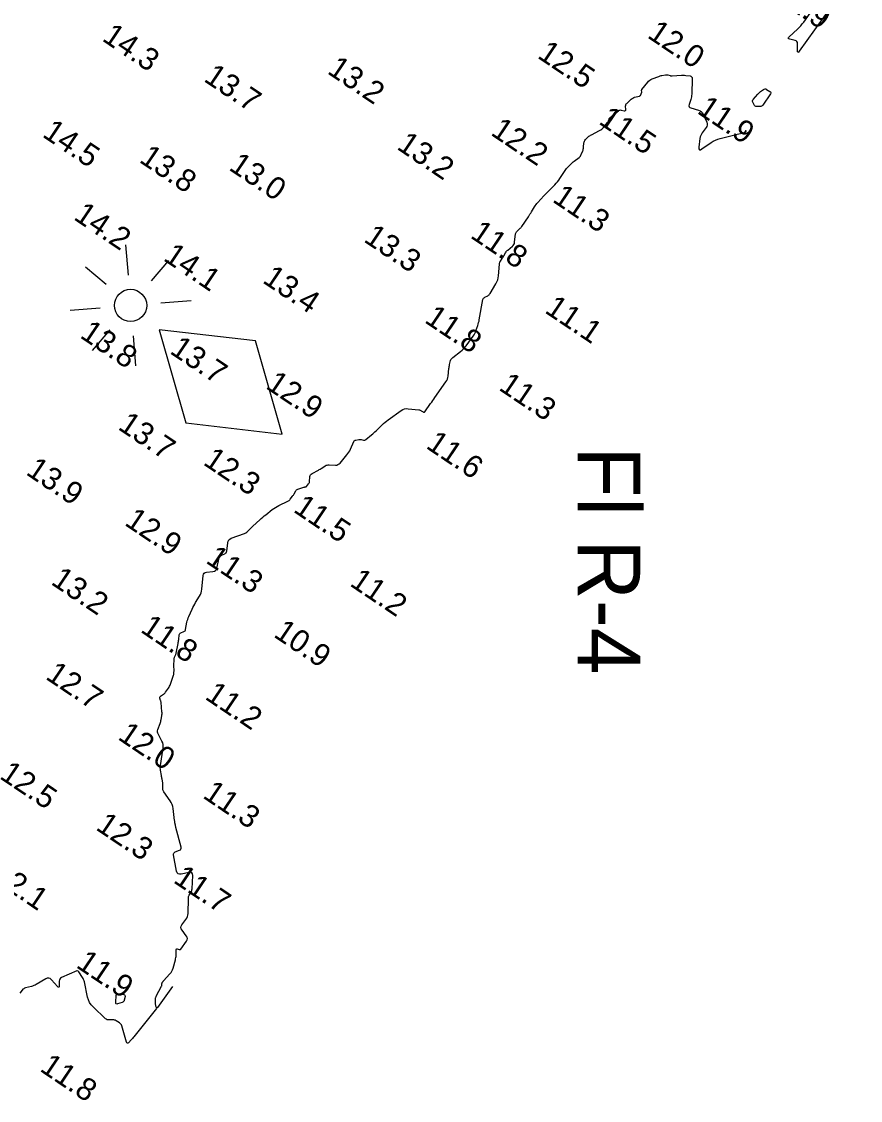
# Model space of a CAD drawing. Extents: x 815352 to 820877, y 582403 to 597439.
# Drawn here: x 816866.2 to 817053.6, y 584137 to 584378.1 of the extents above; entities that cross this region are included whole.
import ezdxf

# ---------------------------------------------------------------- set-up
doc = ezdxf.new("R2010")
doc.units = 0
for name, color, linetype in [('V-CHAN-NAID', 7, 'Continuous'), ('V-CONT-EL12', 7, 'Continuous'), ('V-TOPO-SOUN', 7, 'Continuous')]:
    doc.layers.add(name, color=color, linetype=linetype)

msp = doc.modelspace()

# ---------------------------------------------------------------- linework, layer by layer
at = {"layer": 'V-CHAN-NAID'}
for p, q in [((816889.49, 584328.21), (816890.04, 584321.45)), ((816895.25, 584320.17), (816899.14, 584324.74)), ((816885.1, 584319.34), (816880.53, 584323.23)), ((816897.36, 584315.23), (816904.12, 584315.78)), ((816877.06, 584313.58), (816883.82, 584314.13)), ((816885.93, 584309.19), (816882.04, 584304.62)), ((816891.14, 584307.91), (816891.69, 584301.15))]:
    msp.add_line(p, q, dxfattribs=at)
msp.add_lwpolyline([(816896.99, 584309.24), (816902.94, 584288.44), (816924.43, 584285.93), (816918.48, 584306.73)], close=True, dxfattribs=at)
msp.add_circle((816890.59, 584314.68), 3.6, dxfattribs=at)
at = {"layer": 'V-CONT-EL12'}
for points in [[(817053.62, 584390.67), (817039.95, 584371.49), (817039.77, 584371.27), (817039.64, 584371.23), (817039.57, 584371.34), (817039.55, 584371.62), (817039.59, 584373.18), (817039.55, 584373.45), (817039.45, 584373.66), (817039.27, 584373.82), (817039.01, 584373.91), (817037.83, 584374.18), (817037.6, 584374.26), (817037.5, 584374.38), (817037.53, 584374.53), (817037.69, 584374.72), (817039.57, 584376.45), (817039.95, 584376.81), (817040.31, 584377.2), (817040.64, 584377.6), (817040.96, 584378.02), (817042.91, 584380.77)], [(816899.93, 584162.43), (816896.59, 584157.79), (816896.5, 584157.69), (816896.42, 584157.66), (816896.36, 584157.72), (816896.32, 584157.85), (816896.16, 584158.57), (816896.14, 584158.72), (816896.12, 584158.86), (816896.12, 584159.01), (816896.12, 584159.15), (816896.17, 584159.74), (816896.19, 584159.89), (816896.22, 584160.03), (816896.27, 584160.17), (816896.33, 584160.3), (816897.52, 584162.5), (816897.55, 584162.57), (816897.57, 584162.63), (816897.59, 584162.7), (816897.59, 584162.77), (816897.59, 584163.08), (816897.59, 584163.14), (816897.61, 584163.2), (816897.63, 584163.25), (816897.66, 584163.31), (816897.8, 584163.51), (816897.84, 584163.56), (816897.87, 584163.61), (816897.91, 584163.66), (816897.95, 584163.71), (816899.39, 584165.26), (816899.63, 584165.55), (816899.82, 584165.85), (816899.98, 584166.18), (816900.1, 584166.53), (816900.6, 584168.41), (816900.66, 584168.65), (816900.71, 584168.9), (816900.74, 584169.15), (816900.75, 584169.4), (816900.79, 584170.7), (816900.81, 584170.8), (816900.85, 584170.85), (816900.92, 584170.87), (816901.02, 584170.86), (816901.45, 584170.71), (816901.56, 584170.69), (816901.65, 584170.7), (816901.73, 584170.74), (816901.8, 584170.82), (816903.06, 584172.56), (816903.23, 584172.87), (816903.28, 584173.19), (816903.22, 584173.5), (816903.04, 584173.81), (816902.08, 584175.06), (816901.91, 584175.36), (816901.85, 584175.66), (816901.9, 584175.95), (816902.07, 584176.25), (816902.96, 584177.45), (816903.16, 584177.76), (816903.3, 584178.09), (816903.39, 584178.43), (816903.43, 584178.8), (816903.5, 584182.15), (816903.52, 584182.34), (816903.56, 584182.53), (816903.62, 584182.71), (816903.71, 584182.88), (816904.1, 584183.55), (816904.19, 584183.72), (816904.26, 584183.9), (816904.3, 584184.09), (816904.32, 584184.28), (816904.48, 584187.26), (816904.45, 584187.64), (816904.3, 584187.88), (816904.04, 584187.98), (816903.66, 584187.96), (816901.92, 584187.56), (816901.53, 584187.53), (816901.23, 584187.64), (816901.01, 584187.87), (816900.88, 584188.25), (816900.2, 584191.85), (816900.18, 584192.08), (816900.24, 584192.27), (816900.37, 584192.42), (816900.57, 584192.53), (816901.52, 584192.9), (816901.72, 584193.01), (816901.85, 584193.16), (816901.9, 584193.35), (816901.87, 584193.57), (816900.73, 584198.01), (816900.69, 584198.13), (816900.66, 584198.26), (816900.64, 584198.39), (816900.61, 584198.51), (816900.51, 584199.02), (816900.49, 584199.15), (816900.46, 584199.28), (816900.44, 584199.41), (816900.43, 584199.54), (816900.09, 584202.24), (816900, 584202.7), (816899.86, 584203.14), (816899.67, 584203.56), (816899.43, 584203.95), (816898, 584205.98), (816897.91, 584206.13), (816897.85, 584206.28), (816897.82, 584206.44), (816897.81, 584206.61), (816897.82, 584207.3), (816897.81, 584207.47), (816897.8, 584207.64), (816897.79, 584207.81), (816897.76, 584207.98), (816897.61, 584208.81), (816897.58, 584209.01), (816897.54, 584209.2), (816897.51, 584209.4), (816897.47, 584209.59), (816897.27, 584210.79), (816897.24, 584211.06), (816897.22, 584211.32), (816897.23, 584211.59), (816897.26, 584211.85), (816897.85, 584215.8), (816897.88, 584216.18), (816897.85, 584216.55), (816897.76, 584216.91), (816897.6, 584217.26), (816896.8, 584218.77), (816896.68, 584219.05), (816896.63, 584219.33), (816896.64, 584219.62), (816896.71, 584219.91), (816897.19, 584221.26), (816897.26, 584221.47), (816897.32, 584221.68), (816897.37, 584221.9), (816897.41, 584222.11), (816897.56, 584222.98), (816897.6, 584223.2), (816897.61, 584223.42), (816897.61, 584223.64), (816897.6, 584223.86), (816897.42, 584225.89), (816897.4, 584226.02), (816897.38, 584226.15), (816897.35, 584226.28), (816897.31, 584226.41), (816897.15, 584226.92), (816897.13, 584227.05), (816897.14, 584227.15), (816897.2, 584227.25), (816897.29, 584227.33), (816897.92, 584227.76), (816898.06, 584227.86), (816898.19, 584227.97), (816898.3, 584228.1), (816898.41, 584228.23), (816899.06, 584229.15), (816899.19, 584229.36), (816899.31, 584229.57), (816899.41, 584229.79), (816899.5, 584230.02), (816900.18, 584232.06), (816900.22, 584232.18), (816900.24, 584232.29), (816900.26, 584232.41), (816900.27, 584232.53), (816900.31, 584233.06), (816900.31, 584233.15), (816900.31, 584233.24), (816900.3, 584233.33), (816900.29, 584233.42), (816900.25, 584233.78), (816900.24, 584233.87), (816900.24, 584233.96), (816900.24, 584234.05), (816900.24, 584234.14), (816900.31, 584235.63), (816900.32, 584235.75), (816900.34, 584235.86), (816900.38, 584235.98), (816900.42, 584236.09), (816900.63, 584236.53), (816900.68, 584236.64), (816900.73, 584236.75), (816900.76, 584236.87), (816900.79, 584236.98), (816901.2, 584239.09), (816901.24, 584239.32), (816901.28, 584239.55), (816901.31, 584239.78), (816901.34, 584240.01), (816901.45, 584241.06), (816901.49, 584241.23), (816901.56, 584241.36), (816901.67, 584241.46), (816901.82, 584241.53), (816902.49, 584241.77), (816902.64, 584241.85), (816902.75, 584241.95), (816902.84, 584242.08), (816902.88, 584242.24), (816903.19, 584243.86), (816903.26, 584244.19), (816903.35, 584244.51), (816903.46, 584244.82), (816903.59, 584245.13), (816904.35, 584246.81), (816904.52, 584247.19), (816904.71, 584247.56), (816904.91, 584247.92), (816905.12, 584248.28), (816905.99, 584249.71), (816906.19, 584250.07), (816906.34, 584250.45), (816906.45, 584250.84), (816906.51, 584251.25), (816906.79, 584254.31), (816906.87, 584254.62), (816907.02, 584254.86), (816907.26, 584255.01), (816907.57, 584255.08), (816909, 584255.19), (816909.32, 584255.26), (816909.57, 584255.41), (816909.76, 584255.64), (816909.87, 584255.95), (816910.4, 584258.27), (816910.47, 584258.46), (816910.57, 584258.62), (816910.7, 584258.74), (816910.88, 584258.84), (816911.64, 584259.18), (816911.81, 584259.28), (816911.94, 584259.41), (816912.03, 584259.57), (816912.07, 584259.76), (816912.28, 584261.61), (816912.37, 584261.96), (816912.53, 584262.25), (816912.77, 584262.47), (816913.09, 584262.63), (816916, 584263.67), (816916.19, 584263.75), (816916.37, 584263.85), (816916.54, 584263.98), (816916.69, 584264.12), (816917.27, 584264.74), (816917.42, 584264.9), (816917.57, 584265.05), (816917.72, 584265.2), (816917.88, 584265.34), (816919.47, 584266.78), (816919.79, 584267.06), (816920.12, 584267.34), (816920.45, 584267.62), (816920.78, 584267.88), (816922.22, 584269.04), (816922.57, 584269.3), (816922.93, 584269.54), (816923.3, 584269.75), (816923.68, 584269.95), (816925.68, 584270.89), (816925.85, 584270.99), (816926, 584271.1), (816926.14, 584271.22), (816926.27, 584271.37), (816926.76, 584272.02), (816926.87, 584272.16), (816926.97, 584272.3), (816927.06, 584272.45), (816927.14, 584272.6), (816927.47, 584273.21), (816927.57, 584273.35), (816927.68, 584273.47), (816927.82, 584273.56), (816927.97, 584273.63), (816929.26, 584274.05), (816929.31, 584274.07), (816929.36, 584274.08), (816929.42, 584274.09), (816929.47, 584274.1), (816929.7, 584274.12), (816929.75, 584274.13), (816929.8, 584274.15), (816929.84, 584274.18), (816929.88, 584274.22), (816930.36, 584274.77), (816930.44, 584274.88), (816930.5, 584275), (816930.54, 584275.13), (816930.57, 584275.26), (816930.66, 584276.41), (816930.7, 584276.64), (816930.79, 584276.83), (816930.93, 584276.99), (816931.12, 584277.11), (816932.53, 584277.86), (816932.74, 584277.97), (816932.93, 584278.09), (816933.13, 584278.21), (816933.32, 584278.33), (816934.09, 584278.83), (816934.29, 584278.94), (816934.5, 584279.01), (816934.71, 584279.05), (816934.94, 584279.06), (816936.35, 584278.99), (816936.65, 584279.01), (816936.92, 584279.09), (816937.16, 584279.24), (816937.38, 584279.44), (816938.93, 584281.3), (816939.15, 584281.58), (816939.36, 584281.89), (816939.54, 584282.2), (816939.7, 584282.53), (816940.49, 584284.26), (816940.56, 584284.39), (816940.66, 584284.49), (816940.78, 584284.55), (816940.92, 584284.59), (816941.55, 584284.7), (816941.69, 584284.71), (816941.83, 584284.72), (816941.97, 584284.71), (816942.1, 584284.69), (816942.65, 584284.58), (816942.79, 584284.57), (816942.92, 584284.58), (816943.03, 584284.63), (816943.15, 584284.7), (816944.44, 584285.77), (816944.7, 584285.98), (816944.94, 584286.2), (816945.18, 584286.42), (816945.42, 584286.65), (816946.79, 584287.98), (816947.11, 584288.28), (816947.43, 584288.56), (816947.76, 584288.82), (816948.11, 584289.08), (816951.02, 584291.18), (816951.39, 584291.4), (816951.78, 584291.54), (816952.19, 584291.61), (816952.62, 584291.6), (816955.01, 584291.33), (816955.14, 584291.31), (816955.27, 584291.27), (816955.39, 584291.22), (816955.5, 584291.15), (816955.95, 584290.86), (816956.05, 584290.81), (816956.15, 584290.8), (816956.24, 584290.84), (816956.33, 584290.93), (816957.62, 584292.73), (816957.86, 584293.06), (816958.1, 584293.4), (816958.34, 584293.74), (816958.57, 584294.08), (816961.04, 584297.6), (816961.22, 584297.9), (816961.37, 584298.22), (816961.47, 584298.56), (816961.52, 584298.9), (816961.69, 584300.6), (816961.72, 584300.83), (816961.76, 584301.05), (816961.8, 584301.27), (816961.85, 584301.48), (816962.08, 584302.35), (816962.16, 584302.56), (816962.26, 584302.75), (816962.39, 584302.92), (816962.56, 584303.06), (816964.32, 584304.41), (816964.66, 584304.69), (816964.98, 584305), (816965.28, 584305.32), (816965.55, 584305.67), (816967.13, 584307.84), (816967.31, 584308.11), (816967.47, 584308.39), (816967.61, 584308.68), (816967.72, 584308.98), (816968.15, 584310.21), (816968.26, 584310.51), (816968.34, 584310.83), (816968.42, 584311.14), (816968.48, 584311.46), (816969.29, 584315.97), (816969.34, 584316.14), (816969.43, 584316.29), (816969.54, 584316.41), (816969.69, 584316.51), (816970.36, 584316.84), (816970.52, 584316.94), (816970.66, 584317.05), (816970.79, 584317.18), (816970.89, 584317.33), (816972.2, 584319.51), (816972.42, 584319.93), (816972.59, 584320.37), (816972.71, 584320.83), (816972.77, 584321.31), (816972.97, 584323.93), (816973, 584324.1), (816973.04, 584324.26), (816973.11, 584324.42), (816973.2, 584324.57), (816973.6, 584325.14), (816973.7, 584325.28), (816973.79, 584325.43), (816973.88, 584325.58), (816973.97, 584325.73), (816974.37, 584326.46), (816974.47, 584326.62), (816974.58, 584326.78), (816974.71, 584326.92), (816974.86, 584327.05), (816975.87, 584327.89), (816976.07, 584328.08), (816976.22, 584328.3), (816976.32, 584328.55), (816976.38, 584328.82), (816976.6, 584330.66), (816976.63, 584330.84), (816976.7, 584331), (816976.79, 584331.15), (816976.92, 584331.28), (816977.47, 584331.78), (816977.61, 584331.91), (816977.74, 584332.04), (816977.85, 584332.18), (816977.96, 584332.33), (816979.46, 584334.51), (816979.64, 584334.78), (816979.81, 584335.05), (816979.98, 584335.32), (816980.15, 584335.59), (816980.8, 584336.69), (816980.97, 584336.96), (816981.16, 584337.22), (816981.35, 584337.47), (816981.56, 584337.71), (816982.88, 584339.15), (816983.17, 584339.47), (816983.47, 584339.78), (816983.77, 584340.09), (816984.07, 584340.4), (816985.36, 584341.66), (816985.66, 584341.98), (816985.95, 584342.32), (816986.23, 584342.67), (816986.48, 584343.03), (816987.84, 584345.08), (816987.96, 584345.26), (816988.09, 584345.43), (816988.24, 584345.59), (816988.39, 584345.74), (816989.01, 584346.35), (816989.17, 584346.5), (816989.33, 584346.64), (816989.49, 584346.78), (816989.66, 584346.92), (816990.77, 584347.77), (816990.93, 584347.91), (816991.07, 584348.06), (816991.18, 584348.24), (816991.27, 584348.42), (816991.59, 584349.21), (816991.66, 584349.41), (816991.72, 584349.61), (816991.76, 584349.82), (816991.79, 584350.03), (816991.87, 584350.99), (816991.91, 584351.2), (816991.98, 584351.39), (816992.08, 584351.57), (816992.22, 584351.73), (816992.83, 584352.34), (816992.99, 584352.48), (816993.16, 584352.61), (816993.34, 584352.73), (816993.53, 584352.83), (816995.37, 584353.75), (816995.61, 584353.89), (816995.83, 584354.05), (816996.04, 584354.23), (816996.22, 584354.43), (816997.13, 584355.55), (816997.2, 584355.64), (816997.25, 584355.73), (816997.3, 584355.82), (816997.33, 584355.92), (816997.46, 584356.32), (816997.5, 584356.42), (816997.55, 584356.51), (816997.62, 584356.59), (816997.69, 584356.66), (816999.58, 584358.2), (816999.72, 584358.3), (816999.87, 584358.35), (817000.03, 584358.37), (817000.19, 584358.35), (817000.87, 584358.19), (817001.02, 584358.18), (817001.13, 584358.22), (817001.19, 584358.32), (817001.2, 584358.46), (817001.18, 584359.22), (817001.19, 584359.4), (817001.24, 584359.56), (817001.32, 584359.71), (817001.44, 584359.84), (817002.43, 584360.77), (817002.6, 584360.91), (817002.78, 584361.02), (817002.97, 584361.12), (817003.18, 584361.19), (817004.26, 584361.48), (817004.35, 584361.51), (817004.43, 584361.56), (817004.49, 584361.63), (817004.54, 584361.72), (817004.74, 584362.16), (817004.76, 584362.23), (817004.77, 584362.29), (817004.78, 584362.35), (817004.77, 584362.42), (817004.74, 584362.68), (817004.74, 584362.74), (817004.75, 584362.8), (817004.77, 584362.86), (817004.81, 584362.91), (817006.1, 584364.58), (817006.31, 584364.82), (817006.55, 584365.02), (817006.81, 584365.19), (817007.1, 584365.32), (817008.57, 584365.88), (817008.74, 584365.94), (817008.91, 584365.99), (817009.09, 584366.04), (817009.27, 584366.07), (817010.09, 584366.21), (817010.22, 584366.22), (817010.35, 584366.22), (817010.47, 584366.21), (817010.59, 584366.18), (817011.09, 584366.04), (817011.21, 584366.01), (817011.34, 584366), (817011.46, 584365.99), (817011.59, 584365.99), (817013.62, 584366.14), (817013.87, 584366.15), (817014.11, 584366.15), (817014.35, 584366.13), (817014.59, 584366.1), (817015.56, 584365.98), (817015.77, 584365.92), (817015.92, 584365.8), (817016, 584365.64), (817016.03, 584365.42), (817015.93, 584361.93), (817015.91, 584361.63), (817015.87, 584361.33), (817015.81, 584361.03), (817015.72, 584360.74), (817015.35, 584359.57), (817015.3, 584359.31), (817015.35, 584359.09), (817015.5, 584358.93), (817015.75, 584358.82), (817017.45, 584358.32), (817017.8, 584358.18), (817018.1, 584357.97), (817018.34, 584357.71), (817018.53, 584357.37), (817019.31, 584355.62), (817019.41, 584355.3), (817019.42, 584354.99), (817019.34, 584354.69), (817019.16, 584354.41), (817018.29, 584353.28), (817018.09, 584352.99), (817017.94, 584352.68), (817017.83, 584352.36), (817017.77, 584352.01), (817017.55, 584350.03), (817017.55, 584349.68), (817017.66, 584349.49), (817017.87, 584349.48), (817018.19, 584349.65), (817020.26, 584351.07), (817020.74, 584351.36), (817021.23, 584351.61), (817021.74, 584351.82), (817022.28, 584351.98), (817024.98, 584352.66), (817025.26, 584352.73), (817025.54, 584352.8), (817025.82, 584352.87), (817026.1, 584352.93), (817027.23, 584353.18), (817027.49, 584353.27), (817027.73, 584353.4), (817027.93, 584353.57), (817028.11, 584353.79), (817027.79, 584353.31)], [(816896.39, 584157.51), (816891.29, 584151.19), (816891.15, 584151.02), (816891.01, 584150.86), (816890.86, 584150.69), (816890.72, 584150.53), (816890.13, 584149.89), (816889.99, 584149.78), (816889.87, 584149.75), (816889.78, 584149.83), (816889.7, 584149.99), (816888.6, 584153.66), (816888.53, 584153.85), (816888.42, 584154.03), (816888.29, 584154.18), (816888.12, 584154.31), (816887.4, 584154.78), (816887.21, 584154.89), (816887.02, 584154.96), (816886.82, 584155), (816886.61, 584155), (816885.76, 584154.97), (816885.55, 584154.98), (816885.36, 584155.03), (816885.18, 584155.12), (816885.02, 584155.24), (816882.24, 584157.87), (816881.8, 584158.36), (816881.44, 584158.89), (816881.17, 584159.47), (816880.99, 584160.09), (816880.26, 584163.48), (816880.2, 584163.74), (816880.1, 584163.99), (816879.99, 584164.23), (816879.85, 584164.46), (816879.02, 584165.73), (816878.99, 584165.77), (816878.96, 584165.8), (816878.93, 584165.83), (816878.89, 584165.86), (816878.74, 584165.96), (816878.71, 584165.98), (816878.67, 584165.99), (816878.63, 584165.99), (816878.59, 584165.97), (816875.18, 584164.43), (816874.96, 584164.3), (816874.8, 584164.12), (816874.7, 584163.91), (816874.67, 584163.66), (816874.65, 584162.56), (816874.62, 584162.34), (816874.55, 584162.25), (816874.44, 584162.28), (816874.28, 584162.42), (816872.94, 584163.95), (816872.64, 584164.21), (816872.33, 584164.33), (816871.99, 584164.31), (816871.63, 584164.16), (816869.52, 584162.91), (816869.25, 584162.76), (816868.98, 584162.64), (816868.7, 584162.54), (816868.42, 584162.45), (816867.1, 584162.12), (816866.9, 584162.05), (816866.71, 584161.95), (816866.54, 584161.82), (816866.4, 584161.66), (816865.85, 584160.95)]]:
    msp.add_lwpolyline(points, dxfattribs=at)
for points in [[(817031.69, 584359.3), (817031.55, 584359.2), (817031.39, 584359.14), (817031.2, 584359.13), (817030.41, 584359.14), (817030.24, 584359.17), (817030.1, 584359.23), (817029.99, 584359.33), (817029.89, 584359.48), (817029.59, 584360.13), (817029.53, 584360.29), (817029.53, 584360.45), (817029.57, 584360.59), (817029.67, 584360.73), (817030.72, 584361.91), (817030.86, 584362.06), (817031, 584362.2), (817031.16, 584362.34), (817031.32, 584362.46), (817031.99, 584362.95), (817032.15, 584363.04), (817032.32, 584363.07), (817032.49, 584363.05), (817032.67, 584362.97), (817033.38, 584362.52), (817033.52, 584362.4), (817033.58, 584362.27), (817033.58, 584362.12), (817033.5, 584361.95), (817031.8, 584359.44)], [(816887.41, 584160.56), (816887.44, 584160.62), (816887.49, 584160.66), (816887.55, 584160.7), (816887.85, 584160.8), (816887.92, 584160.82), (816888, 584160.83), (816888.07, 584160.83), (816888.15, 584160.82), (816889.09, 584160.63), (816889.24, 584160.58), (816889.34, 584160.49), (816889.38, 584160.36), (816889.37, 584160.2), (816889.18, 584159.4), (816889.12, 584159.23), (816889.02, 584159.08), (816888.89, 584158.97), (816888.72, 584158.89), (816887.7, 584158.56), (816887.5, 584158.52), (816887.36, 584158.56), (816887.29, 584158.68), (816887.28, 584158.89), (816887.39, 584160.49)]]:
    msp.add_lwpolyline(points, close=True, dxfattribs=at)

# ---------------------------------------------------------------- texts
at = {"layer": 'V-CHAN-NAID'}
msp.add_text('Fl R-4', height=14, rotation=270, dxfattribs=at).set_placement((816990.43, 584283.19))
at = {"layer": 'V-TOPO-SOUN'}
for s, p in [('11.9 ', (817034.04, 584383.44)), ('12.0 ', (817005.79, 584374.69)), ('14.3 ', (816884, 584373.99)), ('12.5 ', (816981.25, 584370.15)), ('13.7 ', (816906.71, 584364.94)), ('13.2 ', (816934.3, 584366.68)), ('11.9 ', (817016.91, 584357.79)), ('11.5 ', (816994.93, 584355.42)), ('14.5 ', (816870.65, 584352.54)), ('12.2 ', (816970.81, 584352.93)), ('13.2 ', (816949.82, 584349.78)), ('13.8 ', (816892.3, 584346.86)), ('13.0 ', (816912.32, 584345.13)), ('11.3 ', (816984.59, 584338)), ('14.2 ', (816877.65, 584334.04)), ('13.3 ', (816942.44, 584329.08)), ('11.8 ', (816966.25, 584329.96)), ('14.1 ', (816897.68, 584324.89)), ('13.4 ', (816919.83, 584319.93)), ('11.1 ', (816982.88, 584313.21)), ('11.8 ', (816956.02, 584311.03)), ('13.8 ', (816879.06, 584307.63)), ('13.7 ', (816899.13, 584304.11)), ('12.9 ', (816920.55, 584296.3)), ('11.3 ', (816972.62, 584295.94)), ('13.7 ', (816887.55, 584287.15)), ('11.6 ', (816956.34, 584282.94)), ('12.3 ', (816906.58, 584279.24)), ('13.9 ', (816866.98, 584277.04)), ('11.5 ', (816926.72, 584268.68)), ('12.9 ', (816889.02, 584265.73)), ('11.3 ', (816907.17, 584257.29)), ('13.2 ', (816872.59, 584252.5)), ('11.2 ', (816939.32, 584252.18)), ('11.8 ', (816892.57, 584241.84)), ('10.9 ', (816922.32, 584240.76)), ('12.7 ', (816871.37, 584231.34)), ('11.2 ', (816906.97, 584226.85)), ('12.0 ', (816887.52, 584217.84)), ('12.5 ', (816861.1, 584209.1)), ('11.3 ', (816906.48, 584204.77)), ('12.3 ', (816882.59, 584197.65)), ('12.1 ', (816859.2, 584186.5)), ('11.7 ', (816899.92, 584185.84)), ('11.9 ', (816878.2, 584166.87)), ('11.8 ', (816870.09, 584143.71))]:
    msp.add_text(s, height=5, rotation=326, dxfattribs=at).set_placement(p)

doc.saveas('drawing.dxf')
